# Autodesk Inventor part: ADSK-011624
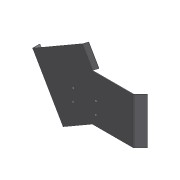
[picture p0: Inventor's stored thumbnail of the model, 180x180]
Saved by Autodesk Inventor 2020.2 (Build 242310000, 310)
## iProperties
Created: 2000-02
Part Number: ADSK-011624
Description: FSHTPH,SS,CP,01,204,165,016,LONG SIDE PAN
Document SubType Name: Tôlerie
Designer: sspink
Material: 1.0312 DC05
Density: 1 g/cm^3
Sheet Metal Rule: Stahlblech 1.0312 - DC05 -   3.0 mm
Appearance: Metal-Steel(Polish)
Mass: 439.634 g
Surface Area: 2988.13 cm^2
Volume: 439.634 cm^3
Flat Pattern Width: 42.9711 cm
Flat Pattern Length: 54.0461 cm
Flat Pattern Area: 2322.42 cm^2
Sheet Metal Width: 429,711 mm
Sheet Metal Length: 540,461 mm
Sheet Metal Area: 232242,185 mm^2
Control State: 0
Master: False
Checked Out: False
Shininess: 57.0
Length Units: 11269
Angle Units: 11279
Time Units: 11290
Mass Units: 11283
Length Display Precision: 3
Angle Display Precision: 2
Compacted: True
Cutlength: 17.31 X 21.83  (378 SI)
Material Desc: SHEET,S/S,11 GAUGE,#2B
Material_Number: A084638
G_L: 429,7x540,5 mm
Thickness: 3,000 mm
Dimensions: 418,4x38x541,9 mm
Mass: 0,44 kg
Semi finished: Stahlblech 1.0312 - DC05 -   3.0 mm
VLT_Material: 1.0312 DC05
Density: 8.03
Volumn: 445.9318843789838
Area: 2866.578471941876
PropertySet Name: Model Information
Author: sspink
Revision Number: -
Title: FSHTPH,SS,CP,01,204,165,016,LONG SIDE PAN
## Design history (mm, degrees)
node "Face1"
  sketch "Sketch1"
    geometry: L1 (0, 0)-(405, 0); L2 (405, 0)-(405, 230); L3 (405, 230)-(0, 230); L4 (0, 230)-(0, 0); L5 (0, 0)-(-101.5, 175.803); L6 (-101.5, 175.803)-(149.968, 320.988); L7 (149.968, 320.988)-(202.5, 230); L8 (0, 0)-(50, -86.603); L9 (50, -86.603)-(200, 0)
    constraints: 18 end point, 4 perpendicular, 2 parallel, 2 point on line, 1 horizontal, 1 midpoint
    dimensions: "d0" = 230 distance between parallel lines of L3 L1; "d1" = 405 distance between parallel lines of L2 L4; "d3" = 60 deg angle of L7 L3; "d4" = 203 distance of L1.start L5.end; "d14" = 100 distance of L1.start L8.end
node "Hole2" dims "d30" = 9, "d31" = 9.525, "d32" = 6.35, "d33" = 60 deg, "d34" = 19.05, "d35" = 118 deg, "d80" = 6
  sketch "Sketch6"
    geometry: L1 (0, -230)-(0, 0) reference; L2 (205, -230)-(0, -230) reference; 4 further points
    constraints: 2 horizontal alignment, 2 vertical alignment
    dimensions: "d25" = 47.5 distance from line of point (188, -182.5) L2; "d27" = 188 distance from line of point (188, -182.5) L1; "d29" = 114 distance of point (302, -122.5) point (188, -122.5); "d36" = 60 distance of point (188, -122.5) point (188, -182.5)
node "Lasche5"
node "Lasche6"
node "Lasche7"
sketch "Skizze11"
  geometry: L1 (16, -67.5)-(16, -92.5); L2 (16, -157.5)-(16, -182.5); L3 (0, -303)-(0, 0) reference; L4 (0, 0)-(32, 0) reference; 1 further point
  constraints: 4 end point, 2 vertical, 1 collinear
  dimensions: "d81" = 25 distance of L1.start L1.end; "d82" = 25 distance of L2.start L2.end (= d81); "d83" = 16 distance between parallel lines of L3 L1; "d84" = 67.5 distance from line of L4 L1.start; "d85" = 65 distance of L2.start L1.end
hole "Bohrung3" sketch "Skizze11" at (16, -67.5), (16, -92.5), (16, -157.5), (16, -182.5) diameter "d86" = 5.5; stored, may be unused: countersink angle "d90" = 90 deg, drill point angle "d92" = 118 deg; dims "d87" = 6, "d88" = 10.4, "d89" = 2, "d91" = 3 (= Thickness)
node "Solide1"
node "Corps solides"
node "Corps surfaciques"
node "Plate1" dims "d49" = 3 (= Thickness)
sketch "Skizze8"
  geometry: L1 (105.064, 0)-(3, 0); L2 (3, 0)-(3, -25); L3 (3, -25)-(105.064, -25); L4 (105.064, -25)-(105.064, 0)
  constraints: 8 end point
feature "Grobblech6" dims "d49" = 3 (= Thickness), "d50" = 3 (= BendReliefWidth), "d51" = 1.5 (= BendReliefDepth), "d52" = 6 (= MinimumRemnant), "d53" = 3 (= TransitionRadius), "d54" = 25, "d55" = 30 deg, "d56" = 3 (= BendRadius), "d57" = 12 (= CornerReliefSize), "d58" = 3 (= TailleJeu), "d59" = 3 (= TailleRayonJacobi), "SeamGap" = 0.00508
feature "Biegung5" dims "d49" = 3 (= Thickness), "d50" = 3 (= BendReliefWidth), "d51" = 1.5 (= BendReliefDepth), "d52" = 6 (= MinimumRemnant), "d53" = 3 (= TransitionRadius), "d54" = 25, "d55" = 30 deg, "d56" = 3 (= BendRadius), "SeamGap" = 0.00508
feature "Ecke1" dims "d54" = 25, "d55" = 30 deg, "d57" = 12 (= CornerReliefSize), "d58" = 3 (= TailleJeu), "d59" = 3 (= TailleRayonJacobi)
sketch "Skizze9"
  geometry: L1 through (151.5, 0) direction (-1, 6.51e-33); L2 through (0, -19) direction (0, -1); L3 (0, -38)-(303, -38); L4 (303, -38)-(303, 0)
  constraints: 6 end point, 1 horizontal, 1 perpendicular, 1 vertical
feature "Grobblech7" dims "d49" = 3 (= Thickness), "d60" = 3 (= BendReliefWidth), "d61" = 1.5 (= BendReliefDepth), "d62" = 6 (= MinimumRemnant), "d63" = 3 (= TransitionRadius), "d64" = 38, "d65" = 90 deg, "d66" = 3 (= BendRadius), "d67" = 12 (= CornerReliefSize), "d68" = 3 (= TailleJeu), "d69" = 3 (= TailleRayonJacobi), "SeamGap" = 0.00508
feature "Biegung6" dims "d49" = 3 (= Thickness), "d60" = 3 (= BendReliefWidth), "d61" = 1.5 (= BendReliefDepth), "d62" = 6 (= MinimumRemnant), "d63" = 3 (= TransitionRadius), "d64" = 38, "d65" = 90 deg, "d66" = 3 (= BendRadius), "SeamGap" = 0.00508
feature "Ecke2" dims "d64" = 38, "d65" = 90 deg, "d67" = 12 (= CornerReliefSize), "d68" = 3 (= TailleJeu), "d69" = 3 (= TailleRayonJacobi)
sketch "Skizze10"
  geometry: L1 through (115, 0) direction (-1, 0); L2 through (0, -25) direction (1.58e-31, -1); L3 (0, -50)-(230, -50); L4 (230, -50)-(230, 0)
  constraints: 6 end point, 1 horizontal, 1 perpendicular, 1 vertical
feature "Grobblech8" dims "d49" = 3 (= Thickness), "d70" = 3 (= BendReliefWidth), "d71" = 1.5 (= BendReliefDepth), "d72" = 6 (= MinimumRemnant), "d73" = 3 (= TransitionRadius), "d74" = 50, "d75" = 45 deg, "d76" = 3 (= BendRadius), "d77" = 12 (= CornerReliefSize), "d78" = 3 (= TailleJeu), "d79" = 3 (= TailleRayonJacobi), "SeamGap" = 0.00508
feature "Biegung7" dims "d49" = 3 (= Thickness), "d70" = 3 (= BendReliefWidth), "d71" = 1.5 (= BendReliefDepth), "d72" = 6 (= MinimumRemnant), "d73" = 3 (= TransitionRadius), "d74" = 50, "d75" = 45 deg, "d76" = 3 (= BendRadius), "SeamGap" = 0.00508
feature "Ecke3" dims "d74" = 50, "d75" = 45 deg, "d77" = 12 (= CornerReliefSize), "d78" = 3 (= TailleJeu), "d79" = 3 (= TailleRayonJacobi)
feature "Definition1"
other parameters: "Thickness" = 3 (derived), "BendRadius" = 3 (= Thickness), "BendReliefWidth" = 3 (= Thickness), "BendReliefDepth" = 1.5 (= 0.5 x Thickness), "CornerReliefSize" = 12 (= 4 x Thickness), "MinimumRemnant" = 6 (= 2 x Thickness), "d2" = 3 (= BendRadius), "d37" = 15.875, "d38" = 45 deg, "d39" = 3 (= BendRadius), "TransitionRadius" = 3 (= BendRadius), "TailleRayonJacobi" = 3 (= BendRadius), "TailleJeu" = 3 (= Thickness), "BendRadius" = 3, "BendReliefDepth" = 1.5, "BendReliefWidth" = 3, "CornerReliefSize" = 12, "MinimumRemnant" = 6, "TailleJeu" = 3, "TailleRayonJacobi" = 3, "Thickness" = 3, "TransitionRadius" = 3
